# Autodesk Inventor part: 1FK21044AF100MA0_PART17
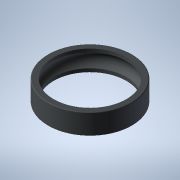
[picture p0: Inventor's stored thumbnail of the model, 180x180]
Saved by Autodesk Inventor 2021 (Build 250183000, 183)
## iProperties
Created: 2025-04
Part Number: 1FK21044AF100MA0_PART17
Material: Generic
Catalog Web Link: www.3dfindit.com
Description: -Servo synchronous motor
Document SubType Name: Modeling
Designer: psAdmin
Mass: 1.64389 g
Surface Area: 26.4305 cm^2
Volume: 1.64389 cm^3
Density: 1 g/cm^3
Appearance: PSOLRGB-212-217-219
Category: PARTsolutions
Title: 1FK21044AF100MA0_PART17
Author: Cadenas PARTsolutions
Comments: Servo synchronous motor
Sending System: PARTsolutions
Preprocessor: ST-DEVELOPER v19.3
PSOL_IDENT_0: {$CADENAS_DATA/23d-libs/siemens_ag/_cat_/ec/e4/1fk21044af100ma0.prj},216 {VTYP=3D},{NB=1FK21044AF100
PSOL_IDENT_1: MA0_PART17},{LINA=1FK21044AF100MA0_PART17},{NN=1FK21044AF100MA0_PART17},{NOPRJ=TRUE},{DATE=19.08.202
PSOL_IDENT_2: 5 14:01:05},{GEOMDATE=30.07.2025 02:01:01},{VERSION=},{LINEID=10},{WBVAR=},{WBNUMERIC=}  {NB=1FK2104
PSOL_IDENT_3: 4AF100MA0_PART17},{LINA=1FK21044AF100MA0_PART17},{KT=DUMMY},{PREVIEW=../../../_pool_/cb/72/p_d211_xx
PSOL_IDENT_4: _00434j.png},{DESCSHORT=SIMOTICS S-1FK2 HD, SINAMICS S210 3AC 400V-480V, 1.27 Nm, 3000 rpm},{DESCLON
PSOL_IDENT_5: G=SIMOTICS S-1FK2 HD servo motor M0=1.27 Nm; PN = 0.4 kW at nN=3000 rpm (380-480 V); PN = 0.2 kW at
PSOL_IDENT_6: nN=1500 rpm (200-240 V); with holding brake; degree of protection IP64; cylindrical shaft D19x40mm;
PSOL_IDENT_7: absolute encoder 22-bit + 12-bit multiturn (encoder AM22DQC); with OCC interface; plug size M17, rot
PSOL_IDENT_8: atable; SIMOTICS S-1FK2 servomotorfor a wide range of uses in industrial environments. SIMOTICS S‑1F
PSOL_IDENT_9: K2 servomotors are compact synchronous motors with a high dynamic performance that set themselves ap
PSOL_IDENT_10: art as a result of their high power density, degree of protection and overload capability. The motor
PSOL_IDENT_11: s are available in two variants: as High Dynamic variant (highest dynamic performance as a result of
PSOL_IDENT_12: the low intrinsic moment of inertia for applications demanding a high dynamic performance with low
PSOL_IDENT_13: moved masses) - and as Compact variant (precise and stable closed-loop control for medium up to larg
PSOL_IDENT_14: e moved masses as a result of a medium intrinsic moment of inertia). SIMOTICSS‑1FK2 servomotors full
PSOL_IDENT_15: y exploit their strengths in a system with the SINAMICSS210 frequency converter and simple connectio
PSOL_IDENT_16: n using the one cable connection (OCC). Advantages include the short control and positioning times,
PSOL_IDENT_17: fast and precise correction of disturbing quantities as well as stable control with a high dynamic p
PSOL_IDENT_18: erformance. The servo motors can be configured to address a wide range of requirements. For example
PSOL_IDENT_19: with and without holding brake, IP64 or IP65 degree of protection, singleturn or multiturn absolute
PSOL_IDENT_20: encoders - to name just a few. Further, the servomotors are available in different shaft heights ext
PSOL_IDENT_21: ending from 20 to 100. A shaft sealing ring is available to achieve an IP65 degree of protection and
PSOL_IDENT_22: for subsequent mounting at the motor or as spare part. SIMOTICS - the optimum motor for each and ev
PSOL_IDENT_23: ery motion control application.},{INTNO=195125043275},{SUPPLIERALTNO=1FK2104-4AF10-0MA0},{MANUID=1FK
PSOL_IDENT_24: 21044AF100MA0},{MANUNAME=Siemens},{MANUTYPEDESC=Synchronous motor 1FK2-HD 1.27 NM},{AAU732=SIMOTICS}
PSOL_IDENT_25: ,{AAO057=S-1FK2},{AAU734=SIMOTICS S-1FK2 HD servo motor M0=1.27 Nm; PN = 0.4 kW at nN=3000 rpm (380-
PSOL_IDENT_26: 480 V); PN = 0.2 kW at nN=1500 rpm (200-240 V); with holding brake; degree of protection IP64; cylin
PSOL_IDENT_27: drical shaft D19x40mm; absolute encoder 22-bit + 12-bit multiturn (encoder AM22DQC); with OCC interf
PSOL_IDENT_28: ace; plug size M17, rotatable;},{AAW338=Synchronous motor 1FK2-HD 1.27 NM},{AAO742=SIMOTICS},{AAO663=
PSOL_IDENT_29: 4042948694015},{NOCUPEROU=1},{PRICEQUANTITY=1},{QUANTITYMIN=1},{QUANTITYINT=1},{CTN=85015100},{COO=D
PSOL_IDENT_30: E},{AAO676=1FK2104-4AF10-0MA0},{AAO677=Siemens AG},{ORDERUNIT=C62},{CONTENTUNIT=C62}
NB: 1FK21044AF100MA0_PART17
NT: Servo synchronous motor
NBSYN: $MANUID._PART17
LINA: 1FK21044AF100MA0_PART17
CATALOG: SIEMENS
PREVIEW: ../../../_pool_/cb/72/p_d211_xx_00434j.png
DESCSHORT: SIMOTICS S-1FK2 HD, SINAMICS S210 3AC 400V-480V, 1.27 Nm, 3000 rpm
DESCLONG: SIMOTICS S-1FK2 HD servo motor M0=1.27 Nm; PN = 0.4 kW at nN=3000 rpm (380-480 V); PN = 0.2 kW at nN=1500 rpm (200-240 V); with holding brake; degree of protect
INTNO: 195125043275
SUPPLIERALTNO: 1FK2104-4AF10-0MA0
MANUID: 1FK21044AF100MA0
MANUNAME: Siemens
MANUTYPEDESC: Synchronous motor 1FK2-HD 1.27 NM
AAU732: SIMOTICS
AAO057: S-1FK2
AAU734: SIMOTICS S-1FK2 HD servo motor M0=1.27 Nm; PN = 0.4 kW at nN=3000 rpm (380-480 V); PN = 0.2 kW at nN=1500 rpm (200-240 V); with holding brake; degree of protect
AAW338: Synchronous motor 1FK2-HD 1.27 NM
AAO742: SIMOTICS
AAO663: 4042948694015.0
NOCUPEROU: 1
PRICEQUANTITY: 1
QUANTITYMIN: 1
QUANTITYINT: 1
CTN: 85015100
COO: DE
ARTICLENO: 1FK21044AF100MA0_PART17
BOMINFO: 1FK21044AF100MA0_PART17
CREATOR: CADENAS GmbH
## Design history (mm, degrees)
feature "2025_04_17_15_33_01_0673"
body "Solid1"
